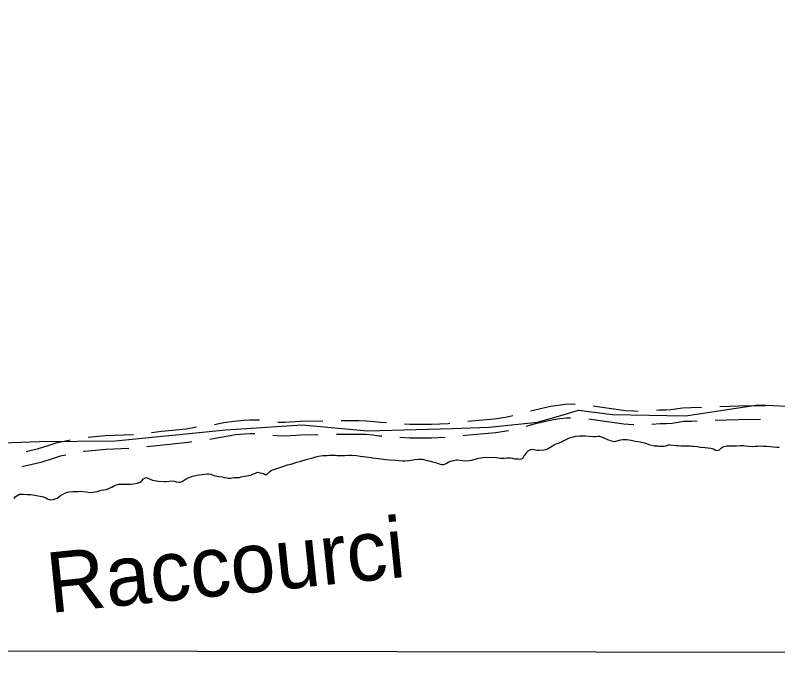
# Model space of a CAD drawing. Extents: x 3192952 to 3230831, y 849296 to 874698.
# Drawn here: x 3198586 to 3200265, y 854674 to 856131 of the extents above; entities that cross this region are included whole.
import ezdxf

# ---------------------------------------------------------------- set-up
doc = ezdxf.new("R2010")
doc.units = 0
for name, color, linetype in [('V-GRID-FRAM', 7, 'Continuous'), ('V-RIVR-IDEN', 7, 'Continuous'), ('V-ROAD-CNTR', 7, 'Continuous'), ('V-SITE-VEGE', 7, 'Continuous'), ('V-TOPO-SHOR', 7, 'Continuous')]:
    doc.layers.add(name, color=color, linetype=linetype)

msp = doc.modelspace()

# ---------------------------------------------------------------- linework, layer by layer
at = {"layer": 'V-GRID-FRAM'}
msp.add_lwpolyline([(3197186.7, 872920.9), (3228554.1, 872861.6), (3228527.7, 854674), (3197144.3, 854733.3), (3197186.7, 872920.9)], dxfattribs=at)
at = {"layer": 'V-ROAD-CNTR'}
for points in [[(3198495.5, 855187.3), (3198638.5, 855192.1), (3198806.7, 855193.7), (3199049.7, 855217.8), (3199217.5, 855228.9), (3199362.3, 855215.6), (3199547.8, 855220.8), (3199629.5, 855223.8), (3199735.9, 855234.9), (3199794.5, 855251.8), (3199826.4, 855261), (3199900.9, 855251.8), (3200062.2, 855248.5), (3200222.2, 855272.7), (3200514.1, 855259.7)], [(3199720.5, 855259.5), (3199727, 855261.3), (3199764.7, 855269.7), (3199781.3, 855272.5), (3199797.2, 855274.1), (3199811.8, 855274.8), (3199819, 855274.4)], [(3199858.8, 855270.8), (3199862.7, 855270.2), (3199929.6, 855260.7), (3199948.1, 855259.4), (3199958, 855259.3)], [(3199997.9, 855261.5), (3200004.5, 855262.1), (3200018.5, 855262), (3200029.7, 855262.5), (3200055.4, 855266.6), (3200074.5, 855267.1), (3200097.5, 855267.8)], [(3200137.5, 855269.1), (3200178.8, 855270.4), (3200237.5, 855271.7)], [(3199582.7, 855237), (3199640.4, 855242.1), (3199665.8, 855246), (3199681.9, 855249.2)], [(3199024.6, 855229.8), (3199045, 855233.7), (3199067.9, 855237.2), (3199088.4, 855239), (3199102.5, 855240.1), (3199123.8, 855239.6)], [(3199163.5, 855235.2), (3199165.6, 855234.9), (3199180.4, 855234.4), (3199213.6, 855236.6), (3199263.4, 855237.7)], [(3199303.4, 855238.4), (3199342.6, 855238.4), (3199359.9, 855237.9), (3199376.4, 855236.5), (3199390, 855234.6), (3199403.2, 855233.7)], [(3199443.1, 855231), (3199454.7, 855230.2), (3199502.2, 855230.5), (3199539.3, 855232), (3199543, 855232.5)], [(3199710.9, 855225.6), (3199734.3, 855232.2), (3199770.5, 855240.3), (3199785.3, 855242.8), (3199799.4, 855244.2), (3199808.8, 855244.6)], [(3199848.7, 855242), (3199858.3, 855240.5), (3199926.4, 855230.8), (3199946.9, 855229.4), (3199947.8, 855229.4)], [(3199987.8, 855230.4), (3200005.8, 855232), (3200019.2, 855232), (3200032.7, 855232.6), (3200058.1, 855236.7), (3200075.3, 855237.1), (3200087.4, 855237.5)], [(3200127.3, 855238.8), (3200179.7, 855240.5), (3200227.3, 855241.5)], [(3198885.8, 855212.2), (3198908.1, 855214.6), (3198962.1, 855220.3), (3198985, 855224.2)], [(3199572.6, 855205.7), (3199585.2, 855207.1), (3199644, 855212.3), (3199671.1, 855216.5), (3199672, 855216.7)], [(3198746.2, 855202), (3198784, 855205.4), (3198845.4, 855207.9), (3198846, 855207.9)], [(3199014.6, 855197.4), (3199050, 855204.1), (3199071.5, 855207.4), (3199090.9, 855209.1), (3199103.3, 855210.1), (3199113.6, 855209.8)], [(3199153.4, 855206.4), (3199162.9, 855205), (3199180.9, 855204.4), (3199214.9, 855206.6), (3199253.2, 855207.4)], [(3199293.2, 855208.3), (3199298.6, 855208.4), (3199342.2, 855208.4), (3199358.1, 855208), (3199373.1, 855206.6), (3199386.9, 855204.7), (3199393, 855204.3)], [(3199432.9, 855201.6), (3199453.8, 855200.2), (3199502.9, 855200.5), (3199532.8, 855201.7)], [(3198610.2, 855170), (3198616, 855171.3), (3198637.4, 855176.6), (3198658.7, 855183.2), (3198678.1, 855189.7), (3198693.6, 855192.7), (3198706.8, 855195.7)], [(3198875.7, 855180.9), (3198911.3, 855184.7), (3198966.2, 855190.5), (3198975, 855192)], [(3198736.1, 855170.7), (3198739.2, 855171.2), (3198786, 855175.5), (3198835.8, 855177.5)], [(3198600.4, 855136.9), (3198623, 855142.2), (3198645.4, 855147.7), (3198668, 855154.6), (3198685.7, 855160.6), (3198696.9, 855162.8)]]:
    msp.add_lwpolyline(points, dxfattribs=at)
at = {"layer": 'V-SITE-VEGE'}
for p, q in [((3199792.5, 855193.3), (3199799, 855196.8)), ((3199799, 855196.8), (3199806.8, 855200.2)), ((3199806.8, 855200.2), (3199812.2, 855201.9)), ((3199812.2, 855201.9), (3199819.8, 855203.7)), ((3199819.8, 855203.7), (3199828.5, 855204.7)), ((3199828.5, 855204.7), (3199836.6, 855204.8)), ((3199836.6, 855204.8), (3199840.9, 855204.4)), ((3199840.9, 855204.4), (3199859.3, 855203.3)), ((3199859.3, 855203.3), (3199863.8, 855203.3)), ((3199863.8, 855203.3), (3199868.9, 855203.8)), ((3199868.9, 855203.8), (3199872.8, 855203.9)), ((3199872.8, 855203.9), (3199880.9, 855201)), ((3199880.9, 855201), (3199889.9, 855196.6)), ((3199889.9, 855196.6), (3199894.4, 855194.9)), ((3199919.5, 855196.1), (3199924, 855196.8)), ((3199924, 855196.8), (3199932.6, 855196.2)), ((3199757.7, 855176.1), (3199768.8, 855182.7)), ((3199768.8, 855182.7), (3199771.5, 855184.1)), ((3199771.5, 855184.1), (3199777.3, 855186.7)), ((3199777.3, 855186.7), (3199784.7, 855189.2)), ((3199784.7, 855189.2), (3199789.2, 855191.3)), ((3199789.2, 855191.3), (3199792.5, 855193.3)), ((3199894.4, 855194.9), (3199898, 855193.8)), ((3199898, 855193.8), (3199902.5, 855192.7)), ((3199902.5, 855192.7), (3199905.9, 855192.3)), ((3199905.9, 855192.3), (3199919.5, 855196.1)), ((3199932.6, 855196.2), (3199942, 855195.2)), ((3199942, 855195.2), (3199945.4, 855194.5)), ((3199945.4, 855194.5), (3199951, 855193)), ((3199951, 855193), (3199962.2, 855191.1)), ((3199962.2, 855191.1), (3199968.3, 855190.3)), ((3199968.3, 855190.3), (3199971.5, 855189.4)), ((3199971.5, 855189.4), (3199976, 855187.5)), ((3199976, 855187.5), (3199980.9, 855185.7)), ((3199980.9, 855185.7), (3199993.8, 855182.3)), ((3199993.8, 855182.3), (3199997.3, 855182.3)), ((3199997.3, 855182.3), (3200001.2, 855182.8)), ((3200001.2, 855182.8), (3200005, 855182.2)), ((3200005, 855182.2), (3200014.9, 855182.1)), ((3200014.9, 855182.1), (3200019.1, 855182.6)), ((3200019.1, 855182.6), (3200023.6, 855184.6)), ((3200023.6, 855184.6), (3200028.5, 855184.7)), ((3200028.5, 855184.7), (3200040.7, 855183.7)), ((3200040.7, 855183.7), (3200046, 855183.5)), ((3200046, 855183.5), (3200052.3, 855182.7)), ((3200052.3, 855182.7), (3200055.9, 855182.5)), ((3200055.9, 855182.5), (3200062.4, 855182.4)), ((3200062.4, 855182.4), (3200072.1, 855182.5)), ((3200072.1, 855182.5), (3200076.1, 855182.1)), ((3200076.1, 855182.1), (3200079.7, 855182.1)), ((3200079.7, 855182.1), (3200087.4, 855181.5)), ((3200087.4, 855181.5), (3200095, 855180)), ((3200095, 855180), (3200105.1, 855179)), ((3200140.8, 855177.1), (3200143.9, 855180.1)), ((3200143.9, 855180.1), (3200152.7, 855182.4)), ((3200152.7, 855182.4), (3200156.7, 855182.9)), ((3200156.7, 855182.9), (3200161.6, 855182.5)), ((3200161.6, 855182.5), (3200174.4, 855182.7)), ((3200174.4, 855182.7), (3200182.1, 855183.4)), ((3200182.1, 855183.4), (3200190.4, 855183.5)), ((3200190.4, 855183.5), (3200193.5, 855182.9)), ((3200193.5, 855182.9), (3200200.7, 855182.1)), ((3200200.7, 855182.1), (3200209.5, 855181.5)), ((3200209.5, 855181.5), (3200216, 855181.6)), ((3200216, 855181.6), (3200221.1, 855181.8)), ((3200221.1, 855181.8), (3200227.6, 855182.8)), ((3200227.6, 855182.8), (3200233.2, 855182.2)), ((3200233.2, 855182.2), (3200241.3, 855181.8)), ((3200241.3, 855181.8), (3200262.9, 855179.8)), ((3200262.9, 855179.8), (3200268.1, 855179.7)), ((3199706.9, 855160.5), (3199711.8, 855166.4)), ((3199711.8, 855166.4), (3199713.1, 855169.1)), ((3199713.1, 855169.1), (3199715.1, 855171.4)), ((3199715.1, 855171.4), (3199721.1, 855174.4)), ((3199721.1, 855174.4), (3199724.3, 855174.9)), ((3199724.3, 855174.9), (3199735.3, 855172.7)), ((3199735.3, 855172.7), (3199740, 855172.8)), ((3199740, 855172.8), (3199749.9, 855173.6)), ((3199749.9, 855173.6), (3199754.6, 855174.5)), ((3199754.6, 855174.5), (3199757.7, 855176.1)), ((3200105.1, 855179), (3200111, 855178.2)), ((3200111, 855178.2), (3200117.5, 855177.6)), ((3200117.5, 855177.6), (3200120.6, 855176.9)), ((3200120.6, 855176.9), (3200125.1, 855175.6)), ((3200125.1, 855175.6), (3200127.8, 855173.4)), ((3200127.8, 855173.4), (3200131.7, 855172.3)), ((3200131.7, 855172.3), (3200136.6, 855173.5)), ((3200136.6, 855173.5), (3200140.8, 855177.1)), ((3199195.6, 855143.3), (3199205.9, 855146.5)), ((3199205.9, 855146.5), (3199212.4, 855148)), ((3199212.4, 855148), (3199219.3, 855150.5)), ((3199219.3, 855150.5), (3199226.9, 855152.8)), ((3199226.9, 855152.8), (3199232.5, 855153.8)), ((3199232.5, 855153.8), (3199235.6, 855154.5)), ((3199235.6, 855154.5), (3199238.8, 855155.6)), ((3199238.8, 855155.6), (3199247.5, 855158.2)), ((3199247.5, 855158.2), (3199254, 855159.9)), ((3199254, 855159.9), (3199263.4, 855161.1)), ((3199263.4, 855161.1), (3199272.4, 855161.6)), ((3199272.4, 855161.6), (3199277.5, 855161.7)), ((3199277.5, 855161.7), (3199286.5, 855162.2)), ((3199286.5, 855162.2), (3199290.8, 855162.3)), ((3199290.8, 855162.3), (3199294.1, 855161.4)), ((3199294.1, 855161.4), (3199298.4, 855161.5)), ((3199298.4, 855161.5), (3199302.2, 855161.3)), ((3199302.2, 855161.3), (3199311, 855161.4)), ((3199311, 855161.4), (3199319.5, 855161.9)), ((3199319.5, 855161.9), (3199323.3, 855162.4)), ((3199323.3, 855162.4), (3199326.7, 855162.4)), ((3199326.7, 855162.4), (3199337.2, 855161)), ((3199337.2, 855161), (3199345.3, 855160.2)), ((3199345.3, 855160.2), (3199358.6, 855158.3)), ((3199358.6, 855158.3), (3199369.4, 855157.1)), ((3199369.4, 855157.1), (3199372.5, 855156.4)), ((3199372.5, 855156.4), (3199391.9, 855154)), ((3199391.9, 855154), (3199402, 855152.5)), ((3199402, 855152.5), (3199409.2, 855152.1)), ((3199409.2, 855152.1), (3199422.4, 855150.7)), ((3199422.4, 855150.7), (3199430.7, 855150.3)), ((3199430.7, 855150.3), (3199438.6, 855149.7)), ((3199438.6, 855149.7), (3199444, 855149.6)), ((3199444, 855149.6), (3199452.5, 855150.1)), ((3199452.5, 855150.1), (3199458.1, 855150.9)), ((3199458.1, 855150.9), (3199466.2, 855152.3)), ((3199466.2, 855152.3), (3199474.5, 855153.5)), ((3199474.5, 855153.5), (3199482.3, 855153.6)), ((3199482.3, 855153.6), (3199493.1, 855150.3)), ((3199493.1, 855150.3), (3199500.3, 855148.6)), ((3199500.3, 855148.6), (3199505.1, 855147.1)), ((3199505.1, 855147.1), (3199511.6, 855145.8)), ((3199536.3, 855144.3), (3199539.4, 855146.4)), ((3199539.4, 855146.4), (3199544.8, 855149.1)), ((3199544.8, 855149.1), (3199556.6, 855151.5)), ((3199556.6, 855151.5), (3199559.8, 855151.5)), ((3199559.8, 855151.5), (3199571.2, 855150.1)), ((3199571.2, 855150.1), (3199580.4, 855149.5)), ((3199580.4, 855149.5), (3199585.4, 855150)), ((3199585.4, 855150), (3199590.8, 855151)), ((3199590.8, 855151), (3199606.9, 855155.4)), ((3199606.9, 855155.4), (3199620.1, 855157.6)), ((3199620.1, 855157.6), (3199645.9, 855156.7)), ((3199645.9, 855156.7), (3199654.2, 855155.7)), ((3199654.2, 855155.7), (3199657.6, 855155.5)), ((3199657.6, 855155.5), (3199662.8, 855155.8)), ((3199662.8, 855155.8), (3199668.1, 855156.5)), ((3199668.1, 855156.5), (3199671.5, 855156.5)), ((3199671.5, 855156.5), (3199676.7, 855155.9)), ((3199676.7, 855155.9), (3199681.2, 855155.1)), ((3199681.2, 855155.1), (3199685.7, 855154)), ((3199685.7, 855154), (3199689.7, 855153.8)), ((3199689.7, 855153.8), (3199693.1, 855153.9)), ((3199693.1, 855153.9), (3199697.8, 855153.5)), ((3199697.8, 855153.5), (3199700.9, 855154)), ((3199700.9, 855154), (3199703.6, 855155.8)), ((3199703.6, 855155.8), (3199706.9, 855160.5)), ((3199149.3, 855128), (3199152.4, 855129.6)), ((3199152.4, 855129.6), (3199155.5, 855130.7)), ((3199155.5, 855130.7), (3199164.5, 855133.1)), ((3199164.5, 855133.1), (3199177.5, 855138.1)), ((3199177.5, 855138.1), (3199181, 855139.3)), ((3199181, 855139.3), (3199185.7, 855140.5)), ((3199185.7, 855140.5), (3199195.6, 855143.3)), ((3199511.6, 855145.8), (3199519.2, 855143.2)), ((3199519.2, 855143.2), (3199525.1, 855141.5)), ((3199525.1, 855141.5), (3199529.4, 855141.8)), ((3199529.4, 855141.8), (3199533.6, 855142.9)), ((3199533.6, 855142.9), (3199536.3, 855144.3)), ((3198870.9, 855111.5), (3198874.3, 855112.6)), ((3198874.3, 855112.6), (3198880.1, 855110.9)), ((3198965.4, 855111.6), (3198969.2, 855113.2)), ((3198969.2, 855113.2), (3198974.8, 855115.1)), ((3198974.8, 855115.1), (3198980.2, 855116.5)), ((3198980.2, 855116.5), (3198989.8, 855118.6)), ((3198989.8, 855118.6), (3198997.6, 855119.6)), ((3198997.6, 855119.6), (3199007.5, 855120.6)), ((3199007.5, 855120.6), (3199012.4, 855120.9)), ((3199012.4, 855120.9), (3199016.3, 855120.2)), ((3199016.3, 855120.2), (3199023.5, 855117.6)), ((3199023.5, 855117.6), (3199033.8, 855115.3)), ((3199033.8, 855115.3), (3199041.9, 855114)), ((3199041.9, 855114), (3199046, 855112.9)), ((3199046, 855112.9), (3199051.6, 855112.1)), ((3199061, 855111.5), (3199067.5, 855112.7)), ((3199067.5, 855112.7), (3199072.5, 855113.2)), ((3199072.5, 855113.2), (3199076.3, 855112.8)), ((3199076.3, 855112.8), (3199079.4, 855112.8)), ((3199079.4, 855112.8), (3199082.8, 855114)), ((3199082.8, 855114), (3199087, 855115.2)), ((3199087, 855115.2), (3199090.4, 855115.9)), ((3199090.4, 855115.9), (3199095.8, 855116.6)), ((3199095.8, 855116.6), (3199105.8, 855118.5)), ((3199105.8, 855118.5), (3199108.7, 855119.9)), ((3199108.7, 855119.9), (3199112.5, 855121.3)), ((3199112.5, 855121.3), (3199115.2, 855122.7)), ((3199115.2, 855122.7), (3199119.5, 855124.5)), ((3199119.5, 855124.5), (3199122.8, 855124.1)), ((3199122.8, 855124.1), (3199132.5, 855121.3)), ((3199132.5, 855121.3), (3199136.6, 855119.7)), ((3199136.6, 855119.7), (3199139.7, 855119.6)), ((3199139.7, 855119.6), (3199142.4, 855121.6)), ((3199142.4, 855121.6), (3199145.7, 855125)), ((3199145.7, 855125), (3199149.3, 855128)), ((3198805.3, 855095.5), (3198808.9, 855096.9)), ((3198808.9, 855096.9), (3198814.3, 855098.5)), ((3198814.3, 855098.5), (3198819, 855098.5)), ((3198819, 855098.5), (3198827.1, 855098)), ((3198827.1, 855098), (3198839.4, 855098.1)), ((3198839.4, 855098.1), (3198845.7, 855099.1)), ((3198845.7, 855099.1), (3198854.9, 855100.7)), ((3198854.9, 855100.7), (3198860.7, 855102.8)), ((3198860.7, 855102.8), (3198863.4, 855104.2)), ((3198863.4, 855104.2), (3198868.2, 855109.6)), ((3198868.2, 855109.6), (3198870.9, 855111.5)), ((3198880.1, 855110.9), (3198883.3, 855108.9)), ((3198883.3, 855108.9), (3198888, 855107.2)), ((3198888, 855107.2), (3198892.8, 855105.9)), ((3198892.8, 855105.9), (3198901.3, 855104.8)), ((3198901.3, 855104.8), (3198914.3, 855104.1)), ((3198914.3, 855104.1), (3198918.1, 855104.1)), ((3198918.1, 855104.1), (3198931.4, 855105.4)), ((3198931.4, 855105.4), (3198935.9, 855104.8)), ((3198935.9, 855104.8), (3198939.9, 855103.5)), ((3198939.9, 855103.5), (3198946.2, 855102.6)), ((3198946.2, 855102.6), (3198949.6, 855102.9)), ((3198949.6, 855102.9), (3198953.6, 855104.1)), ((3198953.6, 855104.1), (3198962.3, 855109.8)), ((3198962.3, 855109.8), (3198965.4, 855111.6)), ((3199051.6, 855112.1), (3199056.1, 855111.7)), ((3199056.1, 855111.7), (3199061, 855111.5)), ((3198695.1, 855078.1), (3198700.9, 855080.9)), ((3198700.9, 855080.9), (3198705.4, 855081.4)), ((3198705.4, 855081.4), (3198713, 855081.7)), ((3198713, 855081.7), (3198716.1, 855082.2)), ((3198716.1, 855082.2), (3198721.1, 855082.2)), ((3198721.1, 855082.2), (3198724.9, 855082)), ((3198724.9, 855082), (3198728.9, 855082.5)), ((3198728.9, 855082.5), (3198734.8, 855082.1)), ((3198734.8, 855082.1), (3198741.7, 855081.1)), ((3198741.7, 855081.1), (3198751.4, 855080.1)), ((3198751.4, 855080.1), (3198756.8, 855080.4)), ((3198756.8, 855080.4), (3198762.2, 855081.1)), ((3198762.2, 855081.1), (3198766, 855081.8)), ((3198766, 855081.8), (3198775.4, 855084.6)), ((3198775.4, 855084.6), (3198781, 855085.6)), ((3198781, 855085.6), (3198786.6, 855086.7)), ((3198786.6, 855086.7), (3198795.1, 855089.8)), ((3198795.1, 855089.8), (3198802.2, 855093.4)), ((3198802.2, 855093.4), (3198805.3, 855095.5)), ((3198583.2, 855066.6), (3198585.9, 855070.4)), ((3198585.9, 855070.4), (3198591.2, 855074.3)), ((3198591.2, 855074.3), (3198595.2, 855075.9)), ((3198595.2, 855075.9), (3198600.2, 855076.4)), ((3198600.2, 855076.4), (3198604.2, 855076.2)), ((3198604.2, 855076.2), (3198612.1, 855075.4)), ((3198612.1, 855075.4), (3198619.7, 855075.1)), ((3198619.7, 855075.1), (3198628.9, 855074)), ((3198628.9, 855074), (3198636.3, 855072.5)), ((3198636.3, 855072.5), (3198640.8, 855071.9)), ((3198640.8, 855071.9), (3198644.9, 855071.1)), ((3198644.9, 855071.1), (3198647.8, 855070)), ((3198647.8, 855070), (3198653, 855067.8)), ((3198653, 855067.8), (3198656.6, 855066)), ((3198656.6, 855066), (3198660.4, 855064.5)), ((3198660.4, 855064.5), (3198664.1, 855063.6)), ((3198664.1, 855063.6), (3198669.4, 855064.4)), ((3198669.4, 855064.4), (3198677.9, 855067.6)), ((3198677.9, 855067.6), (3198684.6, 855072.2)), ((3198684.6, 855072.2), (3198690, 855075.4)), ((3198690, 855075.4), (3198695.1, 855078.1))]:
    msp.add_line(p, q, dxfattribs=at)
at = {"layer": 'V-TOPO-SHOR'}
for points in [[(3199298.4, 855161.5), (3199302.2, 855161.3), (3199311, 855161.4), (3199319.5, 855161.9), (3199323.3, 855162.4), (3199326.7, 855162.4), (3199337.2, 855161), (3199345.3, 855160.2), (3199358.6, 855158.3), (3199369.4, 855157.1), (3199372.5, 855156.4), (3199391.9, 855153.9), (3199402, 855152.5), (3199409.2, 855152.1), (3199422.4, 855150.7), (3199430.7, 855150.3), (3199438.6, 855149.7), (3199444, 855149.6), (3199452.5, 855150.1), (3199458.1, 855150.9), (3199466.2, 855152.3), (3199474.5, 855153.5), (3199482.3, 855153.6), (3199493.1, 855150.3), (3199500.3, 855148.6), (3199505.1, 855147.1), (3199511.6, 855145.8), (3199519.2, 855143.2), (3199525.1, 855141.5), (3199529.4, 855141.8), (3199533.6, 855142.9), (3199536.3, 855144.3), (3199539.4, 855146.4), (3199544.8, 855149.1), (3199556.6, 855151.5), (3199559.8, 855151.5), (3199571.2, 855150.1), (3199580.4, 855149.5), (3199585.4, 855150), (3199590.8, 855151), (3199606.9, 855155.4), (3199620.1, 855157.6), (3199645.9, 855156.7), (3199654.2, 855155.7), (3199657.6, 855155.5), (3199662.8, 855155.8), (3199668.1, 855156.5), (3199671.5, 855156.5), (3199676.7, 855155.9), (3199681.2, 855155.1), (3199685.7, 855154), (3199689.7, 855153.8), (3199693.1, 855153.9), (3199697.8, 855153.5), (3199700.9, 855154), (3199703.6, 855155.8), (3199706.9, 855160.5), (3199711.8, 855166.4), (3199713.1, 855169.1), (3199715.1, 855171.4), (3199721.1, 855174.4), (3199724.3, 855174.9), (3199735.3, 855172.7), (3199740, 855172.8), (3199749.9, 855173.6), (3199754.6, 855174.5), (3199757.7, 855176.1), (3199768.8, 855182.7), (3199771.5, 855184.1), (3199777.3, 855186.7), (3199784.7, 855189.2), (3199789.2, 855191.3), (3199792.5, 855193.3), (3199799, 855196.8), (3199806.8, 855200.2), (3199812.2, 855201.9), (3199819.8, 855203.7), (3199828.5, 855204.7), (3199836.6, 855204.8), (3199840.9, 855204.4), (3199859.3, 855203.3), (3199863.8, 855203.3), (3199868.9, 855203.8), (3199872.8, 855203.9), (3199880.9, 855201), (3199889.9, 855196.6), (3199894.4, 855194.9), (3199898, 855193.8), (3199902.5, 855192.7), (3199905.9, 855192.3), (3199919.5, 855196.1), (3199924, 855196.8), (3199932.6, 855196.2), (3199942, 855195.2), (3199945.4, 855194.5), (3199951, 855193), (3199962.2, 855191.1), (3199968.3, 855190.3), (3199971.5, 855189.4), (3199976, 855187.5), (3199980.9, 855185.7)], [(3199980.9, 855185.7), (3199993.8, 855182.3), (3199997.3, 855182.3), (3200001.2, 855182.8), (3200005, 855182.2), (3200014.9, 855182.1), (3200019.1, 855182.6), (3200023.6, 855184.6), (3200028.5, 855184.7), (3200040.7, 855183.7), (3200046, 855183.5), (3200052.3, 855182.7), (3200055.9, 855182.5), (3200062.4, 855182.4), (3200072.1, 855182.5), (3200076.1, 855182.1), (3200079.7, 855182.1), (3200087.4, 855181.5), (3200095, 855180), (3200105.1, 855179), (3200111, 855178.2), (3200117.5, 855177.6), (3200120.6, 855176.9), (3200125.1, 855175.6), (3200127.8, 855173.4), (3200131.7, 855172.3), (3200136.6, 855173.5), (3200140.8, 855177.2), (3200143.9, 855180.1), (3200152.7, 855182.4), (3200156.7, 855182.9), (3200161.6, 855182.5), (3200174.4, 855182.7), (3200182.1, 855183.4), (3200186.3, 855183.5), (3200190.4, 855183.5), (3200193.5, 855182.9), (3200200.7, 855182.1), (3200209.5, 855181.5), (3200216, 855181.6), (3200221.1, 855181.8), (3200227.6, 855182.8), (3200233.2, 855182.2), (3200241.3, 855181.8), (3200262.9, 855179.8), (3200268.1, 855179.7)], [(3198721.1, 855082.2), (3198724.9, 855082), (3198728.9, 855082.5), (3198734.8, 855082.1), (3198741.7, 855081.1), (3198751.4, 855080.1), (3198756.8, 855080.4), (3198762.2, 855081.1), (3198766, 855081.8), (3198775.4, 855084.6), (3198781, 855085.6), (3198786.6, 855086.7), (3198795.1, 855089.8), (3198798.6, 855091.6), (3198802.2, 855093.4), (3198805.3, 855095.5), (3198808.9, 855096.9), (3198814.3, 855098.5), (3198819, 855098.5), (3198827.1, 855098), (3198839.4, 855098.1), (3198845.7, 855099.1), (3198854.9, 855100.7), (3198860.7, 855102.8), (3198863.4, 855104.2), (3198868.2, 855109.6), (3198870.9, 855111.5), (3198874.3, 855112.6), (3198880.1, 855110.9), (3198883.3, 855108.9), (3198888, 855107.2), (3198892.8, 855105.9), (3198901.3, 855104.8), (3198914.3, 855104.1), (3198918.1, 855104.1), (3198931.4, 855105.4), (3198935.9, 855104.8), (3198939.9, 855103.5), (3198946.2, 855102.6), (3198949.6, 855102.9), (3198953.6, 855104.1), (3198962.3, 855109.8), (3198965.4, 855111.6), (3198969.2, 855113.2), (3198974.8, 855115.1), (3198980.2, 855116.5), (3198989.8, 855118.6), (3198997.6, 855119.6), (3199007.5, 855120.6), (3199012.4, 855120.9), (3199016.3, 855120.2), (3199023.5, 855117.6), (3199033.8, 855115.3), (3199041.9, 855114), (3199046, 855112.9), (3199051.6, 855112.1), (3199056.1, 855111.7), (3199061, 855111.5), (3199067.5, 855112.7), (3199072.5, 855113.2), (3199076.3, 855112.8), (3199079.4, 855112.8), (3199082.8, 855114), (3199087, 855115.2), (3199090.4, 855115.9), (3199095.8, 855116.6), (3199105.8, 855118.5), (3199108.7, 855119.9), (3199112.5, 855121.3), (3199115.2, 855122.7), (3199119.5, 855124.5), (3199122.8, 855124.1), (3199132.5, 855121.3), (3199136.6, 855119.7), (3199139.7, 855119.6), (3199142.4, 855121.6), (3199145.7, 855125), (3199149.3, 855128), (3199152.4, 855129.6), (3199155.5, 855130.7), (3199164.5, 855133.1), (3199177.5, 855138.1), (3199181, 855139.3), (3199185.7, 855140.5), (3199195.6, 855143.3), (3199205.9, 855146.5), (3199212.4, 855148), (3199219.3, 855150.5), (3199226.9, 855152.8), (3199232.5, 855153.8), (3199235.6, 855154.5), (3199238.8, 855155.6), (3199247.5, 855158.2), (3199254, 855159.9), (3199263.4, 855161.1), (3199272.4, 855161.6), (3199277.5, 855161.7), (3199286.5, 855162.2), (3199290.8, 855162.3), (3199294.1, 855161.4), (3199298.4, 855161.5)], [(3198583.2, 855066.6), (3198585.9, 855070.4), (3198591.2, 855074.3), (3198595.2, 855075.9), (3198600.2, 855076.4), (3198604.2, 855076.2), (3198612.1, 855075.4), (3198619.7, 855075.1), (3198628.9, 855074), (3198636.3, 855072.5), (3198640.8, 855071.9), (3198644.9, 855071.1), (3198647.8, 855070), (3198653, 855067.8), (3198656.6, 855066), (3198660.4, 855064.5), (3198664.1, 855063.6), (3198669.4, 855064.4), (3198677.9, 855067.6), (3198684.6, 855072.2), (3198690, 855075.4), (3198695.1, 855078.1), (3198700.9, 855080.9), (3198705.4, 855081.4), (3198713, 855081.7), (3198716.1, 855082.2), (3198721.1, 855082.2)]]:
    msp.add_lwpolyline(points, dxfattribs=at)

# ---------------------------------------------------------------- texts
at = {"layer": 'V-RIVR-IDEN'}
msp.add_text('Raccourci', height=133, rotation=5.8137, dxfattribs=at).set_placement((3198662.3, 854814.1))

doc.saveas('drawing.dxf')
